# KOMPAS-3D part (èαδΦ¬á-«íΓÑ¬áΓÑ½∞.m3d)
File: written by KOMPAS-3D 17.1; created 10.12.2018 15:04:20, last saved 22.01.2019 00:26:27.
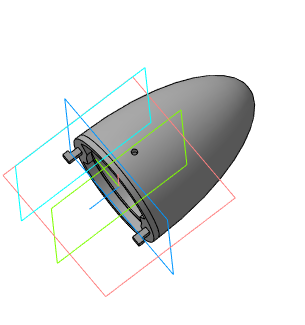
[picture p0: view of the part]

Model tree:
1. Тело-обтекатель
2. Операция вращения:1
     Угол 1 = 360
3. Смещенная плоскость:1
     Расстояние = 17.49
4. Эскиз:5
5. Операция выдавливания:3
     Расстояние 1 = 1; Расстояние 2 = 1
6. Эскиз:8
7. Операция выдавливания:5
     Расстояние 1 = 5
8. Массив по концентрической сетке:2  (with: Операция выдавливания:3, Смещенная плоскость:1)  (2 pattern instances)
     Шаг 2 = 360
9. Эскиз:10
10. Вырезать элемент выдавливания:1
     Расстояние 1 = 3
11. Эскиз:11
12. Вырезать элемент выдавливания:2
     Расстояние 1 = 50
